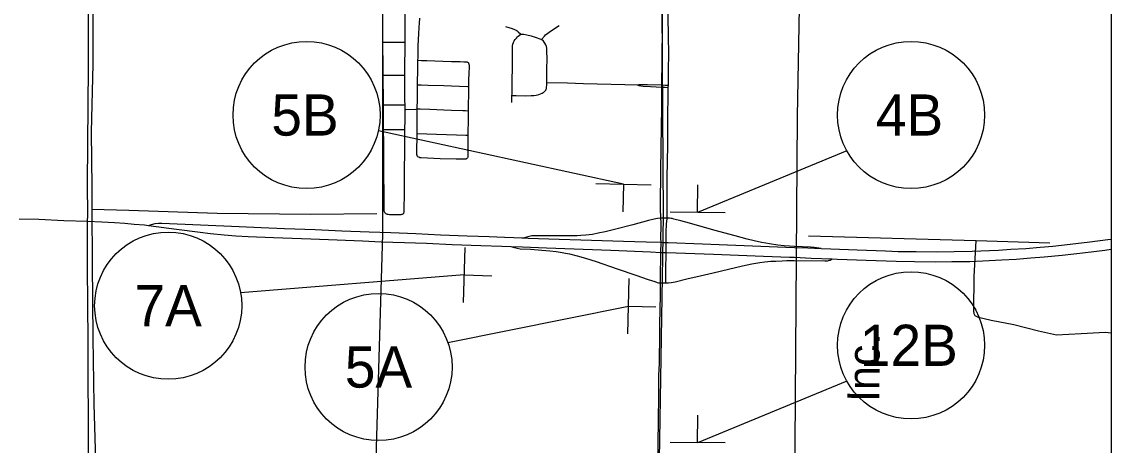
# Model space of a CAD drawing. Extents: x 0 to 680, y 0 to 834.
# Drawn here: x 300.6 to 374.7, y 275.7 to 304.5 of the extents above; entities that cross this region are included whole.
import ezdxf

# ---------------------------------------------------------------- set-up
doc = ezdxf.new("R2010")
doc.units = 0
for name, color, linetype in [('GM_X_City_Street', 7, 'Continuous'), ('GM_X_Interchange_Ramps', 7, 'Continuous'), ('GM_X_Interstate_Route', 7, 'Continuous'), ('GM_X_Minor_River', 7, 'Continuous'), ('GM_X_Rail_Line', 7, 'Continuous'), ('GM_X_Rail_Line_Text', 7, 'Continuous'), ('GM_X_State_Route', 7, 'Continuous'), ('GM_X_Township_Road', 7, 'Continuous'), ('GM_X_US_Route', 7, 'Continuous'), ('SH_Text', 7, 'Continuous')]:
    doc.layers.add(name, color=color, linetype=linetype)

msp = doc.modelspace()

# ---------------------------------------------------------------- linework, layer by layer
at = {"layer": 'GM_X_City_Street'}
msp.add_line((333.944, 299.023), (333.951, 299.502), dxfattribs=at)
for points in [[(325.175, 303.124), (325.169, 303.864), (325.163, 304.604), (325.158, 305.093)], [(326.674, 305.077), (326.67, 304.302), (326.666, 303.456), (326.666, 303.269), (326.664, 303.139)], [(327.558, 301.905), (327.562, 302.097), (327.578, 302.933), (327.592, 303.265), (327.626, 303.746), (327.666, 304.455), (327.679, 304.715), (327.68, 304.766)], [(333.504, 304.188), (333.958, 304.054), (334.124, 303.991), (334.228, 303.936), (334.305, 303.892), (334.381, 303.829), (334.545, 303.671)], [(335.965, 303.31), (336.161, 303.546), (336.24, 303.625), (336.38, 303.741), (336.576, 303.883), (337.165, 304.273)], [(325.175, 303.124), (325.217, 303.124), (326.603, 303.138), (326.664, 303.139)], [(325.193, 300.882), (325.186, 301.573), (325.181, 301.836), (325.18, 302.623), (325.175, 303.124)], [(326.664, 303.139), (326.657, 302.413), (326.646, 301.841), (326.643, 300.876)], [(333.951, 299.502), (333.952, 299.59), (333.967, 300.627), (333.977, 301.29), (333.992, 302.289), (333.987, 302.706), (333.994, 302.884), (334.011, 303.002), (334.046, 303.115), (334.069, 303.169), (334.098, 303.222), (334.168, 303.317), (334.249, 303.404), (334.335, 303.486), (334.375, 303.53), (334.545, 303.671)], [(334.545, 303.671), (334.747, 303.665), (334.97, 303.636), (335.259, 303.559), (335.598, 303.449), (335.845, 303.356), (335.965, 303.31)], [(336.315, 300.4), (336.319, 300.634), (336.323, 300.88), (336.331, 301.394), (336.337, 301.933), (336.324, 302.593), (336.313, 302.716), (336.289, 302.837), (336.27, 302.897), (336.246, 302.955), (336.187, 303.065), (336.099, 303.192), (335.965, 303.31)], [(327.531, 300.235), (327.532, 300.349), (327.546, 301.279), (327.558, 301.905)], [(327.558, 301.905), (327.789, 301.894), (328.171, 301.878), (329.244, 301.839), (329.841, 301.82), (330.121, 301.813), (330.426, 301.805), (330.687, 301.801), (330.81, 301.796), (330.839, 301.794), (330.869, 301.789), (330.899, 301.782), (330.935, 301.764), (330.965, 301.739), (330.985, 301.716), (331.001, 301.691), (331.019, 301.646), (331.024, 301.618), (331.028, 301.586), (331.03, 301.547), (331.033, 301.486), (331.031, 301.348), (331.026, 301.123), (331.003, 300.455), (331.002, 300.36), (330.993, 300.117)], [(325.193, 300.882), (325.504, 300.881), (326.243, 300.878), (326.643, 300.876)], [(325.21, 298.882), (325.205, 299.402), (325.196, 300.499), (325.193, 300.882)], [(326.643, 300.876), (326.642, 300.602), (326.643, 300.006), (326.639, 299.387), (326.644, 299.173), (326.658, 298.866)], [(327.511, 298.589), (327.517, 299.251), (327.531, 300.235)], [(327.531, 300.235), (327.768, 300.229), (328.247, 300.216), (329.323, 300.179), (329.849, 300.161), (330.923, 300.12), (330.993, 300.117)], [(330.993, 300.117), (330.988, 300.007), (330.97, 298.469)], [(333.951, 299.502), (334.118, 299.498), (334.237, 299.495), (334.89, 299.488), (335.247, 299.495), (335.426, 299.509), (335.605, 299.537), (335.781, 299.577), (335.897, 299.615), (336.009, 299.666), (336.062, 299.698), (336.113, 299.734), (336.161, 299.775), (336.204, 299.821), (336.242, 299.873), (336.271, 299.931), (336.291, 299.992), (336.306, 300.067), (336.315, 300.204), (336.315, 300.4)], [(336.315, 300.4), (337.732, 300.365), (338.809, 300.331), (341.623, 300.25), (342.468, 300.226)], [(342.468, 300.226), (342.582, 300.245), (342.714, 300.255), (343.157, 300.258), (344.149, 300.225)], [(342.468, 300.226), (342.575, 300.188), (342.702, 300.161), (342.872, 300.15), (343.359, 300.125), (344.147, 300.076)], [(344.147, 300.076), (344.363, 300.062), (344.58, 300.049)], [(344.149, 300.225), (344.364, 300.218), (344.582, 300.211)], [(325.21, 298.882), (325.431, 298.879), (326.471, 298.868), (326.658, 298.866)], [(325.22, 297.193), (325.218, 297.326), (325.22, 298.113), (325.21, 298.829), (325.21, 298.882)], [(326.669, 298.539), (326.658, 297.862), (326.647, 297.203)], [(326.658, 298.866), (326.669, 298.626), (326.669, 298.539)], [(326.669, 298.539), (326.738, 298.544), (327.404, 298.586), (327.511, 298.589)], [(327.508, 296.931), (327.51, 297.037), (327.506, 297.682), (327.511, 298.589)], [(327.511, 298.589), (327.714, 298.596), (328.359, 298.572), (329.315, 298.534), (329.839, 298.511), (330.603, 298.492), (330.794, 298.48), (330.97, 298.469)], [(330.97, 298.469), (330.964, 297.983), (330.95, 296.816)], [(325.22, 297.193), (325.288, 297.193), (325.57, 297.195), (325.953, 297.192), (326.263, 297.193), (326.429, 297.198), (326.647, 297.203)], [(326.647, 297.203), (326.647, 297.01), (326.642, 296.797), (326.633, 295.63), (326.623, 294.484), (326.623, 293.936), (326.616, 292.961), (326.608, 291.648), (326.606, 291.612), (326.604, 291.584), (326.597, 291.546), (326.578, 291.502), (326.563, 291.482), (326.528, 291.452), (326.477, 291.424), (326.436, 291.409), (326.398, 291.401), (326.354, 291.396), (326.307, 291.395), (325.849, 291.394), (325.681, 291.399), (325.611, 291.403), (325.541, 291.412), (325.491, 291.422), (325.458, 291.431), (325.425, 291.444), (325.379, 291.475), (325.353, 291.496), (325.329, 291.522), (325.308, 291.549), (325.285, 291.583), (325.275, 291.606), (325.265, 291.65), (325.261, 291.693), (325.261, 291.749), (325.259, 291.837), (325.258, 292.601), (325.252, 293.054), (325.243, 293.889), (325.238, 295.035), (325.229, 295.655), (325.233, 296.3), (325.22, 297.193)], [(330.95, 296.816), (330.945, 295.412), (330.945, 295.339), (330.938, 295.306), (330.923, 295.269), (330.886, 295.226), (330.863, 295.21), (330.834, 295.195), (330.803, 295.183), (330.774, 295.177), (330.749, 295.174), (330.724, 295.172), (330.66, 295.172), (330.16, 295.184), (329.065, 295.212), (327.778, 295.268), (327.689, 295.278), (327.608, 295.305), (327.558, 295.338), (327.532, 295.368), (327.504, 295.423), (327.488, 295.487), (327.48, 295.578), (327.508, 296.931)], [(327.508, 296.931), (328.816, 296.878), (330.179, 296.83), (330.819, 296.818), (330.95, 296.816)]]:
    msp.add_lwpolyline(points, dxfattribs=at)
at = {"layer": 'GM_X_Interchange_Ramps'}
for p, q in [((344.494, 291.165), (344.291, 291.168)), ((344.238, 286.767), (344.411, 286.768))]:
    msp.add_line(p, q, dxfattribs=at)
for points in [[(344.291, 291.168), (344.073, 291.165), (344.019, 291.162), (343.85, 291.146), (343.615, 291.105), (343.222, 291.004), (342.16, 290.722), (340.913, 290.393), (340.286, 290.241), (339.819, 290.141), (339.419, 290.072), (338.972, 290.013), (338.629, 289.983), (338.381, 289.97), (338.134, 289.968), (337.369, 289.967), (335.638, 289.979), (335.432, 289.981), (335.31, 289.967), (335.21, 289.95), (335.027, 289.9), (334.8, 289.824)], [(353.167, 289.251), (352.819, 289.266), (352.461, 289.294), (352.034, 289.34), (351.466, 289.422), (351.205, 289.464), (350.925, 289.517), (350.411, 289.627), (349.947, 289.741), (349.117, 289.965), (347.667, 290.366), (346.01, 290.82), (345.434, 290.98), (344.958, 291.11), (344.849, 291.14), (344.763, 291.151), (344.669, 291.162), (344.494, 291.165)], [(333.878, 289.246), (334.111, 289.172), (334.294, 289.122), (334.51, 289.093), (335.202, 289.059), (335.988, 289.007), (336.535, 288.957), (336.961, 288.905), (337.362, 288.842), (337.598, 288.801), (337.852, 288.74), (338.385, 288.607), (338.959, 288.443), (339.663, 288.215), (341.109, 287.723), (342.376, 287.297), (343.21, 287.006), (343.664, 286.859), (343.825, 286.803), (343.912, 286.78), (343.977, 286.773), (344.048, 286.771), (344.238, 286.767)], [(354.977, 289.117), (354.507, 289.181), (354.251, 289.203), (353.167, 289.251)], [(344.411, 286.768), (344.452, 286.768), (344.595, 286.771), (344.784, 286.799), (345.041, 286.853), (345.832, 287.041), (346.74, 287.247), (347.624, 287.453), (348.67, 287.702), (349.624, 287.924), (350.255, 288.057), (350.796, 288.151), (351.151, 288.2), (351.555, 288.243), (351.885, 288.26), (352.312, 288.28), (352.629, 288.289), (353.141, 288.285)], [(353.141, 288.285), (355.218, 288.271), (355.341, 288.275), (355.402, 288.281), (355.467, 288.292), (355.523, 288.307), (355.581, 288.325), (355.731, 288.399)]]:
    msp.add_lwpolyline(points, dxfattribs=at)
at = {"layer": 'GM_X_Interstate_Route'}
msp.add_lwpolyline([(44.693, 394.069), (374.693, 394.069), (374.693, 64.069), (44.693, 64.069)], close=True, dxfattribs=at)
at = {"layer": 'GM_X_Minor_River'}
for points in [[(305.442, 306.343), (305.457, 301.645), (305.341, 297.006), (305.374, 293.286), (305.384, 291.784), (305.402, 288.107), (305.459, 283.016), (305.518, 278.523), (305.638, 274.715), (305.601, 272.206), (305.506, 269.77), (305.455, 267.232), (305.357, 263.614), (305.213, 259.414), (305.146, 256.599), (305.078, 253.404), (305.027, 250.997), (304.976, 248.562), (304.88, 245.732), (304.8, 243.632), (304.805, 240.481), (304.707, 237.068), (304.655, 234.472), (304.603, 231.584)], [(305.384, 291.784), (307.904, 291.718), (313.906, 291.51), (320.244, 291.433), (324.761, 291.478)], [(370.519, 289.477), (365.508, 289.623), (354.115, 289.948)], [(374.693, 283.361), (374.274, 283.398), (372.657, 283.315), (370.966, 283.218), (369.758, 283.484), (368.069, 283.926), (366.54, 284.208), (365.681, 284.429), (365.448, 284.532), (365.376, 284.664), (365.362, 284.882), (365.384, 287.217), (365.508, 289.623)]]:
    msp.add_lwpolyline(points, dxfattribs=at)
at = {"layer": 'GM_X_Rail_Line'}
for points in [[(351.218, 64.069), (351.448, 90.121), (351.798, 116.184), (351.86, 139.423), (352.175, 154.252), (352.451, 189.912), (352.901, 229.863), (353.003, 247.107), (353.355, 298.069), (353.602, 311.675), (353.78, 316.856), (353.954, 319.076), (354.473, 323.516), (355.976, 338.772), (356.265, 341.847), (356.561, 344.985), (356.644, 347.076), (356.685, 349.146), (356.788, 357.395), (356.901, 372.817), (357.146, 391.252), (357.174, 394.069)], [(332.297, 358.476), (331.74, 334.991), (331.623, 332.119), (331.235, 330.489), (330.77, 329.441), (329.838, 328.432), (326.114, 325.676), (325.377, 324.318), (325.144, 323.27), (325.144, 290.084), (324.626, 272.539), (324.407, 251.582), (324.019, 224.102), (323.747, 191.887)], [(341.694, 64.069), (341.887, 75.733), (342.297, 152.995), (342.913, 209.384), (343.255, 230.188), (343.597, 251.334), (344.253, 291.298), (344.078, 319.736), (344.92, 358.256)]]:
    msp.add_lwpolyline(points, dxfattribs=at)
at = {"layer": 'GM_X_State_Route'}
for p, q in [((344.056, 292.511), (344.067, 293.923)), ((344.048, 286.771), (344.048, 286.81))]:
    msp.add_line(p, q, dxfattribs=at)
for points in [[(344.067, 293.923), (344.076, 294.353), (344.096, 295.968), (344.136, 298.718), (344.144, 299.854), (344.147, 300.076), (344.149, 300.225), (344.172, 301.883), (344.182, 304.215), (344.173, 305.591), (344.158, 306.248), (344.168, 307.206), (344.172, 308.134), (344.177, 309.109), (344.177, 309.227), (344.181, 309.284), (344.19, 309.323), (344.211, 309.373), (344.326, 309.597)], [(344.492, 292.464), (344.507, 293.904), (344.54, 296.132), (344.543, 297.562), (344.58, 300.049), (344.582, 300.211), (344.599, 301.317), (344.609, 302.27), (344.602, 303.58), (344.552, 306.082), (344.548, 306.428)], [(344.048, 286.81), (344.048, 287.041), (344.078, 288.848), (344.081, 289.069), (344.086, 289.308), (344.083, 289.529), (344.079, 289.785), (344.093, 290.669), (344.091, 290.878), (344.073, 291.165), (344.051, 291.824), (344.056, 292.511)], [(344.431, 289.327), (344.433, 289.516), (344.436, 289.809), (344.443, 290.354), (344.454, 290.637), (344.46, 290.801), (344.472, 290.928), (344.494, 291.165), (344.493, 291.314), (344.492, 292.464)], [(344.423, 288.683), (344.425, 288.833), (344.431, 289.327)], [(344.411, 286.768), (344.416, 287.78), (344.423, 288.683)], [(343.805, 271.112), (343.813, 271.777), (343.881, 275.833), (343.936, 279.055), (343.938, 280.13), (343.944, 280.486), (343.969, 281.315), (343.992, 283.343), (343.995, 283.94), (344.039, 285.967), (344.048, 286.684), (344.048, 286.771)]]:
    msp.add_lwpolyline(points, dxfattribs=at)
at = {"layer": 'GM_X_Township_Road'}
msp.add_line((305.093, 290.578), (305.097, 290.958), dxfattribs=at)
for points in [[(305.097, 290.958), (305.101, 291.354), (305.097, 293.503), (305.129, 298.875), (305.155, 301.382), (305.167, 304.725), (305.193, 309.262), (305.226, 310.49), (305.255, 310.947)], [(305.204, 272.497), (305.177, 273.206), (305.157, 275.236), (305.123, 282.638), (305.107, 285.503), (305.092, 287.653), (305.089, 290.16), (305.093, 290.578)]]:
    msp.add_lwpolyline(points, dxfattribs=at)
at = {"layer": 'GM_X_US_Route'}
for points in [[(300.452, 291.136), (301.788, 291.093), (303.481, 291.02), (305.097, 290.958), (306.054, 290.926), (306.915, 290.871), (307.626, 290.821), (308.27, 290.771), (308.965, 290.711), (309.246, 290.679)], [(309.246, 290.679), (309.437, 290.744), (309.681, 290.805), (309.915, 290.827), (310.137, 290.829), (315.396, 290.599), (316.898, 290.531), (318.472, 290.47), (320.571, 290.39), (322.383, 290.32), (324.244, 290.251), (325.723, 290.188), (327.416, 290.12), (329.085, 290.049), (330.898, 289.976), (332.4, 289.92), (333.45, 289.876), (334.07, 289.851), (334.619, 289.83), (334.8, 289.824), (335.047, 289.816), (337.165, 289.751), (338.637, 289.707), (341.537, 289.614), (343.083, 289.567), (344.083, 289.529), (344.269, 289.523)], [(309.246, 290.679), (311.139, 290.425), (312.748, 290.209), (313.459, 290.128), (314.385, 290.039), (315.17, 289.978), (316.004, 289.935), (317.744, 289.857), (320.272, 289.768), (322.061, 289.696), (323.779, 289.626), (325.067, 289.572), (326.642, 289.523), (328.145, 289.462), (329.886, 289.387), (331.841, 289.319), (333.249, 289.269), (333.878, 289.246), (334.657, 289.219), (336.303, 289.16), (340.669, 288.988), (343.365, 288.879), (344.078, 288.848), (344.221, 288.842)], [(353.157, 289.185), (354.056, 289.153), (354.977, 289.117), (355.63, 289.09), (357.419, 289.018), (359.351, 288.941), (360.209, 288.915), (361.433, 288.896), (362.872, 288.874), (364.005, 288.908), (365.247, 288.939), (366.415, 288.97), (367.021, 288.993), (367.876, 289.054), (368.887, 289.115), (369.864, 289.192), (370.72, 289.272), (371.893, 289.4), (373.245, 289.554), (374.454, 289.71), (374.693, 289.744)], [(344.269, 289.523), (344.433, 289.516), (344.562, 289.511), (346.9, 289.428), (350.859, 289.272), (352.577, 289.205), (353.157, 289.185)], [(353.114, 288.512), (353.152, 288.51), (354.292, 288.459), (355.731, 288.399), (356.081, 288.385), (358.037, 288.31), (360.064, 288.244), (361.328, 288.218), (362.759, 288.206), (363.857, 288.215), (365.083, 288.236), (365.971, 288.264), (367.26, 288.337), (368.238, 288.393), (369.22, 288.473), (370.124, 288.547), (371.359, 288.666), (372.949, 288.839), (374.251, 289.002), (374.693, 289.064)], [(344.221, 288.842), (344.257, 288.84), (344.425, 288.833), (345.106, 288.804), (347.659, 288.719), (351.047, 288.598), (352.813, 288.525), (353.114, 288.512)]]:
    msp.add_lwpolyline(points, dxfattribs=at)
at = {"layer": 'SH_Text'}
for p, q in [((341.528, 293.48), (324.868, 297.114)), ((356.723, 295.736), (346.574, 291.559)), ((339.653, 293.527), (343.403, 293.432)), ((341.528, 293.48), (341.481, 291.604)), ((346.574, 291.559), (346.59, 293.435)), ((348.45, 291.543), (344.698, 291.574)), ((330.647, 285.436), (330.77, 289.186)), ((330.708, 287.311), (315.499, 286.09)), ((330.708, 287.311), (332.583, 287.249)), ((341.825, 283.322), (341.909, 287.073)), ((329.589, 282.732), (341.867, 285.198)), ((341.867, 285.198), (343.742, 285.156)), ((356.723, 280.086), (346.574, 275.91)), ((346.574, 275.91), (346.59, 277.785)), ((348.45, 275.894), (344.698, 275.925))]:
    msp.add_line(p, q, dxfattribs=at)
for centre in [(319.982, 298.18), (361.085, 298.18), (310.575, 285.225), (361.085, 282.53), (324.877, 281.057)]:
    msp.add_circle(centre, 5, dxfattribs=at)

# ---------------------------------------------------------------- texts
at = {"layer": 'GM_X_Rail_Line_Text'}
msp.add_text('Inc.', height=2.1745, rotation=89.66315, dxfattribs=at).set_placement((358.928, 278.683))
at = {"layer": 'SH_Text'}
for s, p in [('5B', (317.588, 296.78)), ('4B', (358.69, 296.78)), ('7A', (308.281, 283.825)), ('12B', (357.603, 281.13)), ('5A', (322.583, 279.657))]:
    msp.add_text(s, height=2.8, dxfattribs=at).set_placement(p)

doc.saveas('drawing.dxf')
